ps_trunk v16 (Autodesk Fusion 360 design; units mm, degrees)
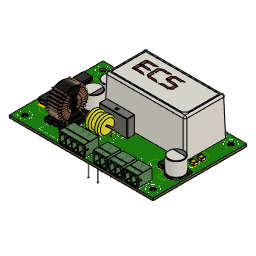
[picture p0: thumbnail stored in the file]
sketch "Outline" plane through (0, 0, 0) normal (0, 0, 1) x axis (1, 0, 0)
  line L1 (92, 0) -> (0, 0)
  line L2 (92, 60) -> (92, 0)
  line L3 (0, 60) -> (92, 60)
  line L4 (0, 0) -> (0, 60)
  line L5 (88.5932, 54.8431) -> (88.6, 54.9476)
  line L6 (88.5795, 54.7392) -> (88.5932, 54.8431)
  line L7 (88.559, 54.6365) -> (88.5795, 54.7392)
  line L8 (88.5319, 54.5353) -> (88.559, 54.6365)
  line L9 (88.4983, 54.4361) -> (88.5319, 54.5353)
  line L10 (88.4582, 54.3393) -> (88.4983, 54.4361)
  line L11 (88.4118, 54.2454) -> (88.4582, 54.3393)
  line L12 (88.3595, 54.1546) -> (88.4118, 54.2454)
  line L13 (88.3013, 54.0675) -> (88.3595, 54.1546)
  line L14 (88.2375, 53.9844) -> (88.3013, 54.0675)
  line L15 (88.1684, 53.9057) -> (88.2375, 53.9844)
  line L16 (88.0943, 53.8316) -> (88.1684, 53.9057)
  line L17 (88.0156, 53.7625) -> (88.0943, 53.8316)
  line L18 (87.9325, 53.6988) -> (88.0156, 53.7625)
  line L19 (87.8454, 53.6406) -> (87.9325, 53.6988)
  line L20 (87.7546, 53.5882) -> (87.8454, 53.6406)
  line L21 (87.6607, 53.5418) -> (87.7546, 53.5882)
  line L22 (87.5639, 53.5017) -> (87.6607, 53.5418)
  line L23 (87.4647, 53.4681) -> (87.5639, 53.5017)
  line L24 (87.3635, 53.441) -> (87.4647, 53.4681)
  line L25 (87.2608, 53.4205) -> (87.3635, 53.441)
  line L26 (87.1569, 53.4069) -> (87.2608, 53.4205)
  line L27 (87.0524, 53.4) -> (87.1569, 53.4069)
  line L28 (86.9476, 53.4) -> (87.0524, 53.4)
  line L29 (86.8431, 53.4069) -> (86.9476, 53.4)
  line L30 (86.7392, 53.4205) -> (86.8431, 53.4069)
  line L31 (86.6365, 53.441) -> (86.7392, 53.4205)
  line L32 (86.5353, 53.4681) -> (86.6365, 53.441)
  line L33 (86.4361, 53.5017) -> (86.5353, 53.4681)
  line L34 (86.3393, 53.5418) -> (86.4361, 53.5017)
  line L35 (86.2454, 53.5882) -> (86.3393, 53.5418)
  line L36 (86.1546, 53.6406) -> (86.2454, 53.5882)
  line L37 (86.0675, 53.6988) -> (86.1546, 53.6406)
  line L38 (85.9844, 53.7625) -> (86.0675, 53.6988)
  line L39 (85.9057, 53.8316) -> (85.9844, 53.7625)
  line L40 (85.8316, 53.9057) -> (85.9057, 53.8316)
  line L41 (85.7625, 53.9844) -> (85.8316, 53.9057)
  line L42 (85.6988, 54.0675) -> (85.7625, 53.9844)
  line L43 (85.6406, 54.1546) -> (85.6988, 54.0675)
  line L44 (85.5882, 54.2454) -> (85.6406, 54.1546)
  line L45 (85.5418, 54.3393) -> (85.5882, 54.2454)
  line L46 (85.5017, 54.4361) -> (85.5418, 54.3393)
  line L47 (85.4681, 54.5353) -> (85.5017, 54.4361)
  line L48 (85.441, 54.6365) -> (85.4681, 54.5353)
  line L49 (85.4205, 54.7392) -> (85.441, 54.6365)
  line L50 (85.4069, 54.8431) -> (85.4205, 54.7392)
  line L51 (85.4, 54.9476) -> (85.4069, 54.8431)
  line L52 (85.4, 55.0524) -> (85.4, 54.9476)
  line L53 (85.4069, 55.1569) -> (85.4, 55.0524)
  line L54 (85.4205, 55.2608) -> (85.4069, 55.1569)
  line L55 (85.441, 55.3635) -> (85.4205, 55.2608)
  line L56 (85.4681, 55.4647) -> (85.441, 55.3635)
  line L57 (85.5017, 55.5639) -> (85.4681, 55.4647)
  line L58 (85.5418, 55.6607) -> (85.5017, 55.5639)
  line L59 (85.5882, 55.7546) -> (85.5418, 55.6607)
  line L60 (85.6406, 55.8454) -> (85.5882, 55.7546)
  line L61 (85.6988, 55.9325) -> (85.6406, 55.8454)
  line L62 (85.7625, 56.0156) -> (85.6988, 55.9325)
  line L63 (85.8316, 56.0943) -> (85.7625, 56.0156)
  line L64 (85.9057, 56.1684) -> (85.8316, 56.0943)
  line L65 (85.9844, 56.2375) -> (85.9057, 56.1684)
  line L66 (86.0675, 56.3013) -> (85.9844, 56.2375)
  line L67 (86.1546, 56.3595) -> (86.0675, 56.3013)
  line L68 (86.2454, 56.4118) -> (86.1546, 56.3595)
  line L69 (86.3393, 56.4582) -> (86.2454, 56.4118)
  line L70 (86.4361, 56.4983) -> (86.3393, 56.4582)
  line L71 (86.5353, 56.5319) -> (86.4361, 56.4983)
  line L72 (86.6365, 56.559) -> (86.5353, 56.5319)
  line L73 (86.7392, 56.5795) -> (86.6365, 56.559)
  line L74 (86.8431, 56.5932) -> (86.7392, 56.5795)
  line L75 (86.9476, 56.6) -> (86.8431, 56.5932)
  line L76 (87.0524, 56.6) -> (86.9476, 56.6)
  line L77 (87.1569, 56.5932) -> (87.0524, 56.6)
  line L78 (87.2608, 56.5795) -> (87.1569, 56.5932)
  line L79 (87.3635, 56.559) -> (87.2608, 56.5795)
  line L80 (87.4647, 56.5319) -> (87.3635, 56.559)
  line L81 (87.5639, 56.4983) -> (87.4647, 56.5319)
  line L82 (87.6607, 56.4582) -> (87.5639, 56.4983)
  line L83 (87.7546, 56.4118) -> (87.6607, 56.4582)
  line L84 (87.8454, 56.3595) -> (87.7546, 56.4118)
  line L85 (87.9325, 56.3013) -> (87.8454, 56.3595)
  line L86 (88.0156, 56.2375) -> (87.9325, 56.3013)
  line L87 (88.0943, 56.1684) -> (88.0156, 56.2375)
  line L88 (88.1684, 56.0943) -> (88.0943, 56.1684)
  line L89 (88.2375, 56.0156) -> (88.1684, 56.0943)
  line L90 (88.3013, 55.9325) -> (88.2375, 56.0156)
  line L91 (88.3595, 55.8454) -> (88.3013, 55.9325)
  line L92 (88.4118, 55.7546) -> (88.3595, 55.8454)
  line L93 (88.4582, 55.6607) -> (88.4118, 55.7546)
  line L94 (88.4983, 55.5639) -> (88.4582, 55.6607)
  line L95 (88.5319, 55.4647) -> (88.4983, 55.5639)
  line L96 (88.559, 55.3635) -> (88.5319, 55.4647)
  line L97 (88.5795, 55.2608) -> (88.559, 55.3635)
  line L98 (88.5932, 55.1569) -> (88.5795, 55.2608)
  line L99 (88.6, 55.0524) -> (88.5932, 55.1569)
  line L100 (88.6, 54.9476) -> (88.6, 55.0524)
  line L101 (88.5932, 4.8431) -> (88.6, 4.9476)
  line L102 (88.5795, 4.7392) -> (88.5932, 4.8431)
  line L103 (88.559, 4.6365) -> (88.5795, 4.7392)
  line L104 (88.5319, 4.5353) -> (88.559, 4.6365)
  line L105 (88.4983, 4.4361) -> (88.5319, 4.5353)
  line L106 (88.4582, 4.3393) -> (88.4983, 4.4361)
  line L107 (88.4118, 4.2454) -> (88.4582, 4.3393)
  line L108 (88.3595, 4.1546) -> (88.4118, 4.2454)
  line L109 (88.3013, 4.0675) -> (88.3595, 4.1546)
  line L110 (88.2375, 3.9844) -> (88.3013, 4.0675)
  line L111 (88.1684, 3.9057) -> (88.2375, 3.9844)
  line L112 (88.0943, 3.8316) -> (88.1684, 3.9057)
  line L113 (88.0156, 3.7625) -> (88.0943, 3.8316)
  line L114 (87.9325, 3.6987) -> (88.0156, 3.7625)
  line L115 (87.8454, 3.6406) -> (87.9325, 3.6987)
  line L116 (87.7546, 3.5882) -> (87.8454, 3.6406)
  line L117 (87.6607, 3.5418) -> (87.7546, 3.5882)
  line L118 (87.5639, 3.5018) -> (87.6607, 3.5418)
  line L119 (87.4647, 3.4681) -> (87.5639, 3.5018)
  line L120 (87.3635, 3.441) -> (87.4647, 3.4681)
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canvas "Canvas1" bodies "Board"
canvas "Canvas2" bodies "Board"
pcbhole "PCBHole1" HoleDepth 1.57 HoleDiameter 3.2 TipAngle 10313.2
pcbhole "PCBHole2" HoleDepth 1.57 HoleDiameter 3.2 TipAngle 10313.2
pcbhole "PCBHole3" HoleDepth 1.57 HoleDiameter 3.2 TipAngle 10313.2
pcbhole "PCBHole4" HoleDepth 1.57 HoleDiameter 3.2 TipAngle 10313.2
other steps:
base_feature "Base Feature1"
base_feature "Base Feature1"
base_feature "Base Feature1"
base_feature "Base Feature1"
base_feature "Base Feature1"
base_feature "Base Feature1"
base_feature "Base Feature1"
base_feature "Base Feature1"
base_feature "Base Feature1"
base_feature "Base Feature1"
base_feature "Base Feature1"
base_feature "Base Feature1"
base_feature "Base Feature1"
base_feature "Base Feature1"
base_feature "Base Feature1"
box_primitive "BoxPrimitive1" DistanceX 1 DistanceY 1 DistanceZ 1 OffsetDistanceX 0 OffsetDistanceY 0
base_feature "Base Feature1"
base_feature "Base Feature1"
base_feature "Base Feature1"
base_feature "Base Feature1"
base_feature "Base Feature1"
base_feature "Base Feature1"
base_feature "Base Feature1"
base_feature "Base Feature1"
base_feature "Base Feature1"
base_feature "Base Feature1"
base_feature "Base Feature1"
base_feature "Base Feature1"
base_feature "Base Feature1"
base_feature "Base Feature1"
extrude "Extrude1" sketch "Outline" blind 1.57 bodies "Board"
pcbextrude "PCBExtrude1"
create_component "CreateComponent1"
create_component "CreateComponent2"
create_component "CreateComponent3"
create_component "CreateComponent1"
create_component "CreateComponent2"
create_component "CreateComponent4"
create_component "CreateComponent1"
create_component "CreateComponent2"
create_component "CreateComponent3"
create_component "CreateComponent4"
create_component "CreateComponent5"
create_component "CreateComponent6"
create_component "CreateComponent6"
create_component "CreateComponent9"
create_component "CreateComponent13"
as_built_joint "As-built1"
create_component "CreateComponent102"
create_component "CreateComponent1"
create_component "CreateComponent2"
create_component "CreateComponent3"
create_component "CreateComponent4"
create_component "CreateComponent1"
create_component "CreateComponent5"
create_component "CreateComponent6"
create_component "CreateComponent109"
create_component "CreateComponent1"
create_component "CreateComponent2"
create_component "CreateComponent110"
create_component "CreateComponent111"
create_component "CreateComponent112"
create_component "CreateComponent113"
create_component "CreateComponent114"
create_component "CreateComponent115"
named bodies: "Board"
